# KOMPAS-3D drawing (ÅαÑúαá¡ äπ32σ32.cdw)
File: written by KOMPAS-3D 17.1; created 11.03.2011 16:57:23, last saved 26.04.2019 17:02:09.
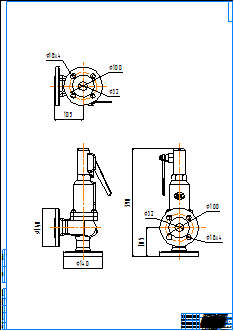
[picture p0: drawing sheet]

Sheet 1: A0, portrait

Title block, sheet 1: name: Прегран Ду32х32; material: Внимание! Данный продукт является объектом авторского права ООО «Торговый Дом АДЛ». / Запрещается изменение, копирование, распространение / (в том числе путем копирования на другие сайты и ресурсы в Интернете) / или любое иное использование информации и объектов без предварительного / согласия правообладателя (ООО «Торговый Дом АДЛ»).; scale: 1:1; sheets: 1; organisation: ООО "Торговый дом АДЛ"; sheet format: A0; stored path: C:\Users\tra\Desktop\2д чертежи\Предохранительные клапаны ПРЕГРАН\ПРЕГРАН 096\ПРЕГРАН КПП 096-03-40\KOMPAS 2D\Прегран Ду32х32.cdw

Views: Спереди 1, Проекционный вид 2, Проекционный вид 3
Dimensions and other numbers on the sheet: 140; 105; 390; 100; 18; 32; 1:1; 1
